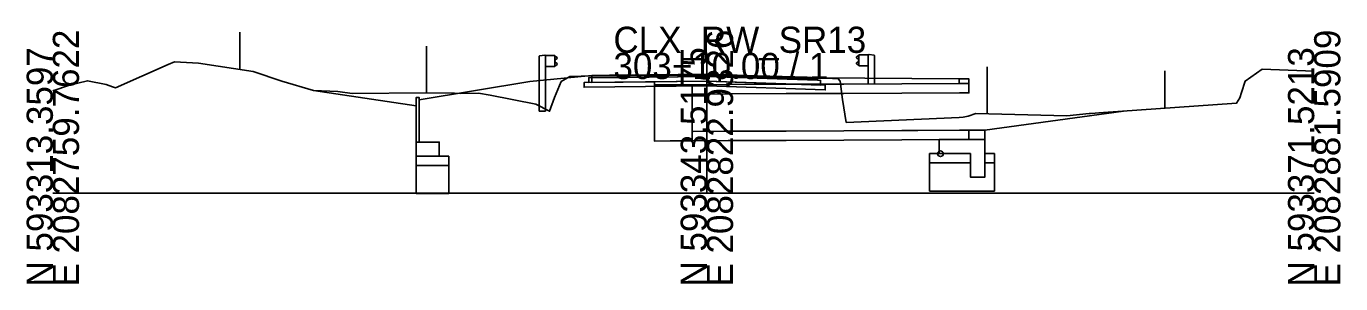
# Model space of a CAD drawing. Extents: x -26 to 2138, y -10 to 4518.
# Drawn here: x 997.2 to 1137.8, y 990.3 to 1017.8 of the extents above; entities that cross this region are included whole.
import ezdxf

# ---------------------------------------------------------------- set-up
doc = ezdxf.new("R2010")
doc.units = 0
for name, color, linetype in [('DR_P_Erosion_Control', 7, 'Continuous'), ('GK_Cells', 7, 'Continuous'), ('MD_P_Surface_Aggregate_Base', 7, 'Continuous'), ('MD_P_Surface_Asphalt_Concrete_Base', 7, 'Continuous'), ('MD_P_Surface_Asphalt_Concrete_Intermediate_Course', 7, 'Continuous'), ('MD_P_Surface_Asphalt_Concrete_Surface_Course', 7, 'Continuous'), ('MD_P_Surface_Non-Reinforced_Concrete_Pavement', 7, 'Continuous'), ('PV_P_EOP', 7, 'Continuous'), ('RD_P_Cells', 7, 'Continuous'), ('RW_P_Esmt_SH', 7, 'Continuous'), ('RW_X_Esmt_SH', 7, 'Continuous'), ('SC_Scratch1', 7, 'Continuous'), ('UT_X_Water', 7, 'Continuous'), ('XS_P_Excavation_Limits', 7, 'Continuous'), ('XS_P_Finished_Grade', 7, 'Continuous'), ('XS_X_Ground_Line', 7, 'Continuous')]:
    doc.layers.add(name, color=color, linetype=linetype)

msp = doc.modelspace()

# ---------------------------------------------------------------- linework, layer by layer
at = {"layer": 'DR_P_Erosion_Control'}
for p, q in [((1038.88, 1009.32), (1027.91, 1010.98)), ((1099.76, 1006.72), (1099.76, 1005.72))]:
    msp.add_line(p, q, dxfattribs=at)
at = {"layer": 'GK_Cells'}
for p, q in [((1070, 1000), (1070, 1015)), ((1000, 1000), (1070, 1000)), ((1070, 1000), (1135, 1000))]:
    msp.add_line(p, q, dxfattribs=at)
at = {"layer": 'MD_P_Surface_Aggregate_Base'}
for points in [[(1070, 1011.96), (1070, 1011.46), (1056.86, 1011.33), (1056.86, 1011.83), (1070, 1011.96)], [(1070, 1011.96), (1070, 1011.46), (1082.67, 1011.04), (1082.67, 1011.54), (1070, 1011.96)]]:
    msp.add_lwpolyline(points, dxfattribs=at)
at = {"layer": 'MD_P_Surface_Asphalt_Concrete_Base'}
for points in [[(1070, 1012.46), (1070, 1011.96), (1057.36, 1011.84), (1057.36, 1012.34), (1070, 1012.46)], [(1070, 1012.46), (1070, 1011.96), (1082.17, 1011.56), (1082.17, 1012.06), (1081.83, 1012.07), (1070, 1012.46)]]:
    msp.add_lwpolyline(points, dxfattribs=at)
at = {"layer": 'MD_P_Surface_Asphalt_Concrete_Intermediate_Course'}
for points in [[(1070, 1012.61), (1070, 1012.46), (1057.69, 1012.34), (1057.69, 1012.49), (1070, 1012.61)], [(1070, 1012.61), (1070, 1012.46), (1081.83, 1012.07), (1081.83, 1012.22), (1070, 1012.61)]]:
    msp.add_lwpolyline(points, dxfattribs=at)
at = {"layer": 'MD_P_Surface_Asphalt_Concrete_Surface_Course'}
for points in [[(1070, 1012.71), (1070, 1012.61), (1057.69, 1012.49), (1057.69, 1012.59), (1070, 1012.71)], [(1070, 1012.71), (1070, 1012.61), (1081.83, 1012.22), (1081.83, 1012.32), (1070, 1012.71)]]:
    msp.add_lwpolyline(points, dxfattribs=at)
at = {"layer": 'MD_P_Surface_Non-Reinforced_Concrete_Pavement'}
for points in [[(1068.41, 1005.59), (1066.08, 1005.58), (1064.38, 1005.57), (1064.38, 1011.57), (1066.08, 1011.58), (1068.41, 1011.59), (1068.41, 1005.59)], [(1098.04, 1011.72), (1097.05, 1011.72), (1090.85, 1011.69), (1084.66, 1011.66), (1078.47, 1011.64), (1072.27, 1011.61), (1068.52, 1011.59), (1068.41, 1011.59), (1068.41, 1010.59), (1068.52, 1010.59), (1072.27, 1010.61), (1078.47, 1010.64), (1084.66, 1010.66), (1090.85, 1010.69), (1097.05, 1010.72), (1098.04, 1010.72), (1098.04, 1011.72)], [(1098.04, 1011.72), (1097.01, 1011.72), (1097.01, 1012.22), (1098.04, 1012.22), (1098.04, 1011.72)], [(1038.88, 1005.46), (1039.2, 1005.46), (1039.2, 1010.23), (1038.88, 1010.21), (1038.88, 1005.46)], [(1098.04, 1006.72), (1097.05, 1006.72), (1092.57, 1006.7), (1090.85, 1006.69), (1084.66, 1006.66), (1078.47, 1006.64), (1072.27, 1006.61), (1068.52, 1006.59), (1068.41, 1006.59), (1068.41, 1005.59), (1068.52, 1005.59), (1072.27, 1005.61), (1078.47, 1005.64), (1084.66, 1005.66), (1090.85, 1005.69), (1097.05, 1005.72), (1098.04, 1005.72), (1098.04, 1006.72)], [(1038.88, 1004.36), (1038.88, 1003.96), (1041.35, 1003.96), (1041.35, 1004.88), (1041.35, 1005.46), (1038.88, 1005.46), (1038.88, 1004.36)], [(1099.76, 1005.72), (1099.76, 1003.91), (1099.76, 1001.72), (1098.38, 1001.72), (1098.21, 1001.72), (1098.21, 1001.89), (1098.21, 1004.22), (1097.94, 1004.22), (1096.26, 1004.22), (1094.86, 1004.22), (1094.86, 1004.57), (1094.86, 1005.72), (1096.55, 1005.72), (1097.94, 1005.72), (1099.76, 1005.72)]]:
    msp.add_lwpolyline(points, dxfattribs=at)
at = {"layer": 'PV_P_EOP'}
msp.add_line((1081.83, 1012.32), (1097.01, 1012.22), dxfattribs=at)
at = {"layer": 'RD_P_Cells'}
for p, q in [((1052.1, 1014.68), (1052.05, 1014.66)), ((1052.05, 1008.76), (1052.05, 1014.66)), ((1052.64, 1014.76), (1052.1, 1014.68)), ((1052.72, 1014.72), (1052.64, 1014.76)), ((1053.72, 1014.72), (1052.72, 1014.72)), ((1052.72, 1008.76), (1052.72, 1014.72)), ((1053.72, 1013.53), (1053.72, 1014.72)), ((1053.81, 1014.62), (1053.72, 1014.64)), ((1053.76, 1014.24), (1053.97, 1014.38)), ((1053.97, 1014.51), (1053.81, 1014.62)), ((1086.03, 1014.58), (1086.19, 1014.7)), ((1086.24, 1014.31), (1086.03, 1014.45)), ((1086.19, 1014.7), (1086.28, 1014.71)), ((1086.28, 1013.61), (1086.28, 1014.79)), ((1086.28, 1014.79), (1087.28, 1014.79)), ((1087.28, 1014.79), (1087.36, 1014.84)), ((1087.28, 1011.67), (1087.28, 1014.79)), ((1087.36, 1014.84), (1087.9, 1014.75)), ((1087.9, 1014.75), (1087.95, 1014.73)), ((1087.95, 1011.68), (1087.95, 1014.73)), ((1053.72, 1013.53), (1052.72, 1013.53)), ((1053.72, 1013.62), (1053.81, 1013.63)), ((1053.73, 1014.13), (1053.73, 1014.18)), ((1053.73, 1014.08), (1053.73, 1014.13)), ((1053.97, 1013.88), (1053.76, 1014.02)), ((1053.81, 1013.63), (1053.97, 1013.75)), ((1086.03, 1013.95), (1086.24, 1014.09)), ((1086.19, 1013.71), (1086.03, 1013.82)), ((1086.28, 1013.69), (1086.19, 1013.71)), ((1086.27, 1014.2), (1086.27, 1014.25)), ((1086.27, 1014.15), (1086.27, 1014.2)), ((1086.28, 1013.61), (1087.28, 1013.61)), ((1052.72, 1008.76), (1052.05, 1008.76))]:
    msp.add_line(p, q, dxfattribs=at)
for points in [[(1053.74, 1014.19), (1053.74, 1014.07), (1053.73, 1014.07), (1053.73, 1014.19)], [(1053.74, 1014.16), (1053.74, 1014.1), (1053.76, 1014.1), (1053.76, 1014.16)], [(1086.26, 1014.23), (1086.26, 1014.17), (1086.24, 1014.17), (1086.24, 1014.23)], [(1086.26, 1014.26), (1086.26, 1014.14), (1086.27, 1014.14), (1086.27, 1014.26)]]:
    msp.add_lwpolyline(points, close=True, dxfattribs=at)
for centre, start, end in [((1053.92, 1014.45), 304.962, 54.7677), ((1086.08, 1014.52), 125.2323, 235.038), ((1053.81, 1014.18), 124.962, 180), ((1053.81, 1014.08), 180, 235.038), ((1053.92, 1013.81), 304.962, 54.7677), ((1086.08, 1013.88), 125.2323, 235.038), ((1086.19, 1014.25), 0, 55.038), ((1086.19, 1014.15), 304.962, 0)]:
    msp.add_arc(centre, 0.0781, start, end, dxfattribs=at)
at = {"layer": 'RW_P_Esmt_SH'}
for p, q in [((1020, 1013.22), (1020, 1017.22)), ((1119, 1009.08), (1119, 1013.08))]:
    msp.add_line(p, q, dxfattribs=at)
at = {"layer": 'RW_X_Esmt_SH'}
for p, q in [((1040, 1010.72), (1040, 1015.72)), ((1100, 1008.49), (1100, 1013.49))]:
    msp.add_line(p, q, dxfattribs=at)
at = {"layer": 'SC_Scratch1'}
for p, q in [((1056.19, 1012.44), (1057.69, 1012.59)), ((1057.69, 1012.59), (1070, 1012.71)), ((1057.69, 1012.49), (1070, 1012.61)), ((1057.69, 1012.59), (1057.69, 1011.84)), ((1057.69, 1012.34), (1070, 1012.46)), ((1057.69, 1011.84), (1064.38, 1011.91)), ((1064.38, 1011.57), (1064.38, 1011.91)), ((1070, 1012.71), (1081.83, 1012.32)), ((1070, 1012.61), (1081.83, 1012.22)), ((1070, 1012.46), (1081.83, 1012.07)), ((1081.83, 1012.32), (1081.83, 1012.07))]:
    msp.add_line(p, q, dxfattribs=at)
at = {"layer": 'UT_X_Water'}
msp.add_circle((1095, 1004.21), 0.3, dxfattribs=at)
at = {"layer": 'XS_P_Excavation_Limits'}
for p, q in [((1038.88, 1003.96), (1038.88, 999.96)), ((1041.35, 1003.96), (1042.38, 1003.96)), ((1042.38, 999.96), (1042.38, 1003.96)), ((1093.82, 1000.22), (1093.82, 1004.22)), ((1094.86, 1004.22), (1093.82, 1004.22)), ((1098.21, 1003.22), (1093.82, 1003.22)), ((1099.76, 1004.22), (1100.79, 1004.22)), ((1099.76, 1003.22), (1100.79, 1003.22)), ((1100.79, 1000.22), (1100.79, 1004.22)), ((1038.88, 1002.96), (1042.38, 1002.96)), ((1038.88, 999.96), (1042.38, 999.96)), ((1100.79, 1000.22), (1093.82, 1000.22))]:
    msp.add_line(p, q, dxfattribs=at)
at = {"layer": 'XS_P_Finished_Grade'}
for p, q in [((1051.05, 1011.93), (1039.2, 1009.96)), ((1056.19, 1012.44), (1051.05, 1011.93)), ((1099.76, 1006.72), (1114.59, 1008.76)), ((1098.04, 1006.72), (1099.76, 1006.72))]:
    msp.add_line(p, q, dxfattribs=at)
at = {"layer": 'XS_X_Ground_Line'}
msp.add_lwpolyline([(1000, 1010.95), (1001.77, 1011.55), (1003.72, 1012.01), (1005.72, 1011.62), (1006.38, 1011.38), (1006.71, 1011.26), (1012.34, 1013.75), (1013.02, 1014.05), (1015.59, 1013.91), (1021.44, 1012.99), (1024.52, 1011.97), (1027.91, 1010.98), (1030.51, 1010.86), (1032.02, 1010.64), (1039.93, 1010.72), (1042.98, 1010.68), (1043.62, 1010.67), (1045.56, 1010.68), (1046.81, 1010.47), (1051.71, 1009.5), (1053.17, 1008.76), (1053.68, 1010.23), (1054.42, 1011.93), (1055.34, 1012.48), (1057.72, 1012.53), (1059.58, 1012.61), (1062.07, 1012.62), (1070.16, 1012.72), (1072.74, 1012.63), (1080.74, 1012.39), (1081.14, 1012.36), (1082.25, 1012.33), (1084.07, 1012.24), (1084.27, 1011.96), (1084.53, 1010.02), (1084.91, 1007.56), (1096.99, 1008.09), (1097.42, 1008.12), (1097.95, 1008.23), (1098.78, 1008.53), (1108.54, 1008.25), (1110.92, 1008.5), (1111.06, 1008.51), (1111.55, 1008.54), (1111.94, 1008.57), (1126.69, 1009.63), (1127.04, 1010.2), (1127.22, 1010.76), (1127.62, 1011.98), (1129.45, 1013.24), (1135, 1013.04)], dxfattribs=at)

# ---------------------------------------------------------------- texts
msp.add_text('-', height=0.0001).set_placement((1000, 1000))
at = {"layer": 'GK_Cells'}
for s, p in [('E 2082759.7622', (1002.8, 990)), ('E 2082822.9326', (1072.8, 990)), ('E 2082881.5909', (1137.8, 990)), ('N 593313.3597', (1000, 990)), ('N 593343.5175', (1070, 990)), ('N 593371.5213', (1135, 990))]:
    msp.add_text(s, height=2.8, rotation=90, dxfattribs=at).set_placement(p)
for s, p in [('CLX_RW_SR13', (1060, 1015)), ('303+10.00 / 1', (1060, 1012.2))]:
    msp.add_text(s, height=2.8, dxfattribs=at).set_placement(p)

doc.saveas('drawing.dxf')
